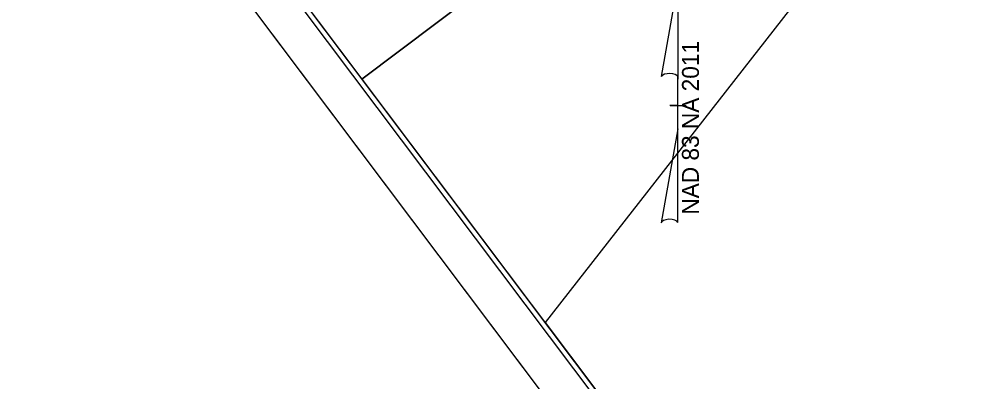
# Model space of a CAD drawing. Extents: x 1262749 to 1264921, y 774795 to 776798.
# Drawn here: x 1263033.3 to 1263520.3, y 775796.4 to 775978.2 of the extents above; entities that cross this region are included whole.
import ezdxf

# ---------------------------------------------------------------- set-up
doc = ezdxf.new("R2010")
doc.units = 0
for name, color, linetype in [('Old_Level_1', 7, 'Continuous'), ('Sheet Clip Boundary CELL', 7, 'Continuous'), ('Sheet Cutting Line CELL', 7, 'Continuous'), ('Sheet Layout Plan Border', 7, 'Continuous'), ('Sheet Plan CELL', 7, 'Continuous'), ('Sheet Plan Layout CELL', 7, 'Continuous'), ('Sheet Plot Border Inside CELL', 7, 'Continuous'), ('Sheet Plot Border Outside CELL', 7, 'Continuous')]:
    doc.layers.add(name, color=color, linetype=linetype)

msp = doc.modelspace()

# ---------------------------------------------------------------- linework, layer by layer
at = {"layer": 'Old_Level_1'}
for p, q in [((1263355.96, 775949.6), (1263364.18, 775995.95)), ((1263364.23, 775995.95), (1263364.21, 775948.15)), ((1263364.2, 775923.35), (1263364.21, 775949.55)), ((1263364.21, 775948.15), (1263364.21, 775949.5)), ((1263360.21, 775934.95), (1263360.16, 775934.95)), ((1263363.76, 775934.95), (1263360.21, 775934.95)), ((1263360.26, 775934.95), (1263368.26, 775934.94)), ((1263364.2, 775923.35), (1263355.83, 775876.1)), ((1263364.23, 775876.3), (1263364.2, 775923.35))]:
    msp.add_line(p, q, dxfattribs=at)
for centre, start_param, end_param in [((1263360.1, 775949.1), 0.216388, 2.908219), ((1263360.07, 775875.93), 0.201328, 3.141593)]:
    msp.add_ellipse(centre, major_axis=(4.23, -0.03), ratio=0.461098, start_param=start_param, end_param=end_param, dxfattribs=at)
at = {"layer": 'Sheet Clip Boundary CELL'}
msp.add_lwpolyline([(1264772.58, 775612.83), (1264136.13, 776457.81), (1263888.68, 776271.43), (1263888.68, 776271.43), (1263542.03, 776010.32), (1263546.69, 776013.84), (1263492.14, 776075.03), (1263297.42, 775826.09), (1263933.87, 774981.11)], close=True, dxfattribs=at)
at = {"layer": 'Sheet Cutting Line CELL'}
msp.add_line((1263033.3, 776139.38), (1264046.16, 774794.65), dxfattribs=at)
at = {"layer": 'Sheet Layout Plan Border'}
msp.add_lwpolyline([(1264772.58, 775612.83), (1263930.27, 776731.11), (1263260.5, 776226.63), (1263374.36, 776075.45), (1263205.44, 775948.22), (1263933.87, 774981.11)], close=True, dxfattribs=at)
at = {"layer": 'Sheet Plan CELL'}
msp.add_lwpolyline([(1263061.47, 776139.35), (1263963.95, 774941.17), (1264802.66, 775572.89), (1263900.19, 776771.05)], close=True, dxfattribs=at)
at = {"layer": 'Sheet Plan Layout CELL'}
for points in [[(1263963.99, 774941.16), (1264802.66, 775572.89), (1263900.2, 776771.04), (1263230.42, 776266.56), (1263374.36, 776075.45), (1263205.44, 775948.22)], [(1263374.36, 776075.45), (1263230.41, 776266.58), (1263061.46, 776139.36), (1263205.44, 775948.22)]]:
    msp.add_lwpolyline(points, close=True, dxfattribs=at)
at = {"layer": 'Sheet Plot Border Inside CELL'}
msp.add_lwpolyline([(1264897.01, 775451.8), (1263894.68, 776782.53), (1263051.98, 776147.82), (1264054.31, 774817.07)], close=True, dxfattribs=at)
at = {"layer": 'Sheet Plot Border Outside CELL'}
msp.add_lwpolyline([(1264920.81, 775453.45), (1263907.95, 776798.18), (1263033.3, 776139.38), (1264046.16, 774794.65)], close=True, dxfattribs=at)

# ---------------------------------------------------------------- texts
at = {"layer": 'Old_Level_1'}
msp.add_text('NAD 83 NA 2011', height=8.5, rotation=89.9761, dxfattribs=at).set_placement((1263374.71, 775880.2))

doc.saveas('drawing.dxf')
